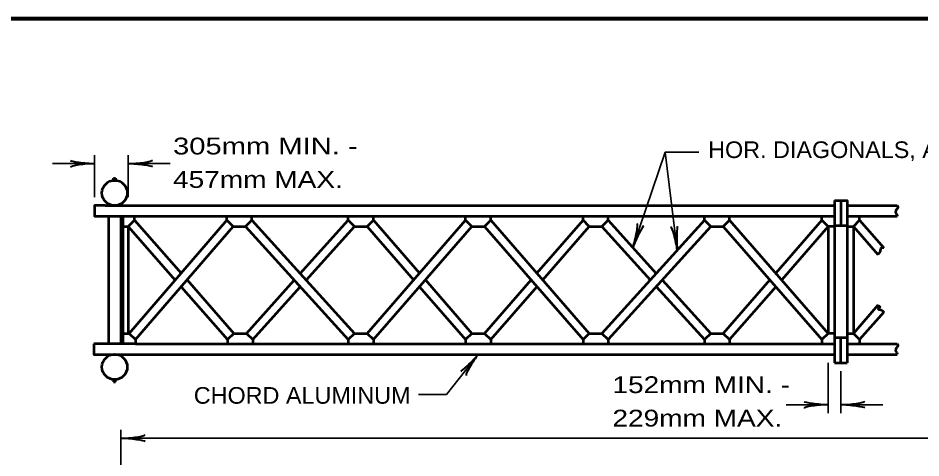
# Model space of a CAD drawing. Extents: x -29 to 827, y -14 to 530.
# Drawn here: x 166.5 to 296.8, y 459.8 to 523.3 of the extents above; entities that cross this region are included whole.
import ezdxf

# ---------------------------------------------------------------- set-up
doc = ezdxf.new("R2010")
doc.units = 0
doc.header["$LTSCALE"] = 0.97
doc.layers.add('1', color=7, linetype='Continuous', lineweight=53)

msp = doc.modelspace()

# ---------------------------------------------------------------- linework, layer by layer
at = {"layer": '1', "lineweight": 35}
for p, q in [((177.5755, 497.4045), (177.5755, 503.4525)), ((182.4475, 497.4045), (182.4475, 503.4525)), ((259.9246, 503.8997), (264.7716, 503.8997)), ((171.5275, 502.2525), (177.5755, 502.2525)), ((182.4475, 502.2525), (188.4955, 502.2525)), ((283.4155, 473.5245), (283.4155, 466.2765)), ((285.2395, 472.3245), (285.2395, 466.2765)), ((283.4155, 467.4765), (277.3675, 467.4765)), ((285.2395, 467.4765), (291.2875, 467.4765)), ((181.3915, 424.6845), (181.3915, 463.8525)), ((181.3915, 462.6285), (412.9195, 462.6285))]:
    msp.add_line(p, q, dxfattribs=at)
at = {"layer": '1'}
for p, q in [((180.3355, 500.1405), (180.6235, 500.1405)), ((180.3355, 499.8285), (180.3355, 500.1405)), ((180.6235, 500.1405), (180.6235, 499.8285)), ((284.3275, 496.9485), (284.3275, 473.5245)), ((285.2395, 496.9485), (285.2395, 493.3245)), ((179.0875, 496.2045), (284.3275, 496.2045)), ((286.1515, 496.2045), (293.3995, 496.2045)), ((179.5675, 494.6925), (179.5675, 476.2365)), ((181.3915, 494.6925), (181.3915, 476.2365)), ((181.6795, 494.6925), (181.6795, 476.2365)), ((182.4475, 493.1805), (183.3595, 494.0925)), ((182.5675, 477.7485), (196.6555, 494.0925)), ((183.3595, 494.0925), (183.3595, 494.6925)), ((183.3595, 494.6925), (231.1195, 494.6925)), ((183.3595, 494.0925), (190.0555, 486.4365)), ((196.6555, 494.0925), (196.6555, 494.6925)), ((197.5675, 493.1805), (196.6555, 494.0925)), ((199.3675, 493.1805), (200.2795, 494.0925)), ((200.2795, 494.0925), (200.2795, 494.6925)), ((200.2795, 494.0925), (215.0875, 477.7485)), ((207.2635, 486.3885), (214.1755, 494.0925)), ((214.1755, 494.0925), (214.1755, 494.6925)), ((215.0875, 493.1805), (214.1755, 494.0925)), ((216.9115, 477.7485), (231.1195, 494.0925)), ((216.9115, 493.1805), (217.8235, 494.0925)), ((217.8235, 494.0925), (217.8235, 494.6925)), ((217.8235, 494.0925), (224.4715, 486.4365)), ((231.1195, 494.0925), (231.1195, 494.6925)), ((232.0315, 493.1805), (231.1195, 494.0925)), ((233.8315, 493.1805), (234.7435, 494.0925)), ((234.7435, 494.0925), (234.7435, 494.6925)), ((234.7435, 494.0925), (248.9515, 477.7485)), ((241.3915, 486.4365), (248.0635, 494.0925)), ((248.0635, 494.0925), (248.0635, 494.6925)), ((248.9515, 493.1805), (248.0635, 494.0925)), ((250.7755, 493.1805), (251.6875, 494.0925)), ((265.5835, 494.0925), (250.7755, 477.7485)), ((251.6875, 494.0925), (251.6875, 494.6925)), ((251.6875, 494.0925), (258.6235, 486.4125)), ((265.5835, 494.0925), (265.5835, 494.6925)), ((266.4955, 493.1805), (265.5835, 494.0925)), ((268.2955, 493.1805), (269.2075, 494.0925)), ((269.2075, 494.0925), (269.2075, 494.6925)), ((269.2075, 494.0925), (283.4155, 477.7485)), ((282.5275, 494.0925), (275.8555, 486.4365)), ((282.5275, 494.0925), (282.5275, 494.6925)), ((283.4155, 493.1805), (282.5275, 494.0925)), ((286.1515, 494.6925), (293.3995, 494.6925)), ((287.0635, 493.1805), (287.9515, 494.0925)), ((287.9515, 494.0925), (287.9515, 494.6925)), ((287.9515, 494.0925), (291.4315, 490.0845)), ((181.6795, 493.1805), (182.4475, 493.1805)), ((182.4475, 493.1805), (189.2155, 485.4525)), ((182.4475, 493.1805), (182.4475, 477.7485)), ((183.4795, 476.8605), (197.5675, 493.1805)), ((199.3675, 493.1805), (214.1755, 476.8605)), ((208.1275, 485.4285), (215.0875, 493.1805)), ((216.9115, 493.1805), (223.6075, 485.4765)), ((217.8235, 476.8605), (232.0315, 493.1805)), ((233.8315, 493.1805), (248.0635, 476.8605)), ((242.2555, 485.4765), (248.9515, 493.1805)), ((250.7755, 493.1805), (257.7595, 485.4765)), ((266.4955, 493.1805), (251.6875, 476.8605)), ((268.2955, 493.1805), (282.5275, 476.8605)), ((283.4155, 493.1805), (276.7195, 485.4765)), ((284.3275, 493.1805), (283.4155, 493.1805)), ((283.4155, 493.1805), (283.4155, 477.7485)), ((284.3275, 493.3245), (286.1515, 493.3245)), ((286.1515, 493.1805), (287.0635, 493.1805)), ((287.0635, 493.1805), (287.0635, 477.7485)), ((287.0635, 493.1805), (290.5915, 489.1245)), ((190.9195, 485.4765), (197.6875, 477.7485)), ((199.5115, 477.7485), (206.3995, 485.4285)), ((225.3115, 485.4765), (232.0315, 477.7485)), ((233.8315, 477.7485), (240.5515, 485.4765)), ((259.4875, 485.4765), (266.4955, 477.7485)), ((275.0155, 485.4765), (268.2955, 477.7485)), ((190.0555, 484.4925), (196.7755, 476.8605)), ((200.3995, 476.8605), (207.2635, 484.4685)), ((224.4715, 484.4925), (231.1195, 476.8605)), ((234.7435, 476.8605), (241.3915, 484.4925)), ((258.6235, 484.5165), (265.5835, 476.8605)), ((275.8555, 484.4925), (269.2075, 476.8605)), ((290.5915, 481.8285), (287.0635, 477.7485)), ((291.4315, 480.8445), (287.9515, 476.8605)), ((181.6795, 477.7485), (182.5675, 477.7485)), ((182.5675, 477.7485), (183.4795, 476.8605)), ((183.4795, 476.8605), (183.4795, 476.2365)), ((197.6875, 477.7485), (196.7755, 476.8605)), ((196.7755, 476.8605), (196.7755, 476.2365)), ((197.6875, 477.7485), (199.5115, 477.7485)), ((199.5115, 477.7485), (200.3995, 476.8605)), ((200.3995, 476.8605), (200.3995, 476.2365)), ((215.0875, 477.7485), (214.1755, 476.8605)), ((214.1755, 476.8605), (214.1755, 476.2365)), ((215.0875, 477.7485), (216.9115, 477.7485)), ((216.9115, 477.7485), (217.8235, 476.8605)), ((217.8235, 476.8605), (217.8235, 476.2365)), ((232.0315, 477.7485), (231.1195, 476.8605)), ((231.1195, 476.8605), (231.1195, 476.2365)), ((232.0315, 477.7485), (233.8315, 477.7485)), ((233.8315, 477.7485), (234.7435, 476.8605)), ((234.7435, 476.8605), (234.7435, 476.2365)), ((248.9515, 477.7485), (248.0635, 476.8605)), ((248.0635, 476.8605), (248.0635, 476.2365)), ((248.9515, 477.7485), (250.7755, 477.7485)), ((250.7755, 477.7485), (251.6875, 476.8605)), ((251.6875, 476.8605), (251.6875, 476.2365)), ((266.4955, 477.7485), (265.5835, 476.8605)), ((265.5835, 476.8605), (265.5835, 476.2365)), ((266.4955, 477.7485), (268.2955, 477.7485)), ((268.2955, 477.7485), (269.2075, 476.8605)), ((269.2075, 476.8605), (269.2075, 476.2365)), ((283.4155, 477.7485), (282.5275, 476.8605)), ((282.5275, 476.8605), (282.5275, 476.2365)), ((284.3275, 477.7485), (283.4155, 477.7485)), ((284.3275, 477.1485), (286.1515, 477.1485)), ((285.2395, 473.5245), (285.2395, 477.1485)), ((286.1515, 477.7485), (287.0635, 477.7485)), ((287.0635, 477.7485), (287.9515, 476.8605)), ((287.9515, 476.8605), (287.9515, 476.2365)), ((179.5675, 476.2365), (177.4555, 476.2365)), ((183.4795, 476.2365), (231.1195, 476.2365)), ((286.1515, 476.2365), (293.3995, 476.2365)), ((178.9435, 474.7245), (284.3275, 474.7245)), ((286.1515, 474.7245), (293.3995, 474.7245)), ((284.3275, 473.5245), (286.1515, 473.5245)), ((180.3355, 471.1005), (180.3355, 470.7885)), ((180.3355, 470.7885), (180.6235, 470.7885)), ((180.6235, 470.7885), (180.6235, 471.1005))]:
    msp.add_line(p, q, dxfattribs=at)
at = {"layer": '1', "lineweight": 158}
msp.add_lwpolyline([(820.0407, 523.2545), (28.3407, 523.1545), (28.4407, -2.8455)], dxfattribs=at)
at = {"layer": '1', "lineweight": 35}
for points in [[(255.2327, 490.167), (259.9246, 503.8997), (261.6496, 489.7505)], [(232.9483, 474.7245), (228.3353, 468.9563), (224.324, 468.9563)]]:
    msp.add_lwpolyline(points, dxfattribs=at)
at = {"layer": '1'}
for points in [[(284.3275, 496.9485), (286.1515, 496.9485), (286.1515, 473.5245)], [(179.0875, 496.2045), (177.5755, 496.2045), (177.5755, 494.6925), (183.3595, 494.6925)], [(231.1195, 494.6925), (234.7435, 494.6925), (282.5275, 494.6925), (284.3275, 494.6925)], [(197.5675, 493.1805), (198.4795, 493.1805), (199.3675, 493.1805)], [(215.0875, 493.1805), (215.9995, 493.1805), (216.9115, 493.1805)], [(232.0315, 493.1805), (232.9435, 493.1805), (233.8315, 493.1805)], [(248.9515, 493.1805), (249.8635, 493.1805), (250.7755, 493.1805)], [(266.4955, 493.1805), (267.4075, 493.1805), (268.2955, 493.1805)], [(177.4555, 476.2365), (177.4555, 474.7245), (178.9435, 474.7245)], [(183.4795, 476.2365), (181.3915, 476.2365), (179.5675, 476.2365)], [(231.1195, 476.2365), (234.7435, 476.2365), (282.5275, 476.2365), (284.3275, 476.2365)]]:
    msp.add_lwpolyline(points, dxfattribs=at)
for centre in [(180.4765, 498.0179), (180.4765, 472.9187)]:
    msp.add_circle(centre, 1.8265, dxfattribs=at)
at = {"layer": '1', "lineweight": 40}
for centre, major_axis, ratio, start_param, end_param in [((176.2674, 501.9173), (2.16, 0.1889), 0.122415, 0.89635335, 3.14159265), ((176.2674, 501.9173), (2.16, 0.1889), 0.122415, 0.89635335, 3.14159265), ((176.232, 502.5075), (2.1246, -0.2125), 0.07063, 3.14071475, 5.41810995), ((176.232, 502.5075), (2.1246, -0.2125), 0.07063, 3.14071475, 5.41810995), ((183.7964, 501.9956), (-2.1246, 0.2125), 0.07063, 3.14071475, 5.41810995), ((183.761, 502.5857), (-2.16, -0.1889), 0.122415, 0.89635335, 3.14159265), ((255.3423, 491.5133), (-0.5155, -2.0883), 0.122415, 0.89635335, 3.14159265), ((255.9077, 491.3573), (0.8809, 1.9264), 0.07063, 6.28230741, 8.55970261), ((261.162, 491.0102), (0.4453, -2.1044), 0.122415, 0.89635335, 3.14159265), ((261.7389, 491.1159), (-0.0458, 2.1178), 0.07063, 6.28230741, 8.55970261), ((231.9102, 473.833), (-1.481, -1.5144), 0.07063, 6.28230741, 8.55970261), ((232.3894, 473.4948), (1.192, 1.7905), 0.122415, 0.89635335, 3.14159265), ((282.072, 467.7315), (2.1246, -0.2125), 0.07063, 3.14071475, 5.41810995), ((286.5617, 467.8097), (-2.16, -0.1889), 0.122415, 0.89635335, 3.14159265), ((286.5617, 467.8097), (-2.16, -0.1889), 0.122415, 0.89635335, 3.14159265), ((282.1074, 467.1413), (2.16, 0.1889), 0.122415, 0.89635335, 3.14159265), ((286.5971, 467.2196), (-2.1246, 0.2125), 0.07063, 3.14071475, 5.41810995), ((286.5971, 467.2196), (-2.1246, 0.2125), 0.07063, 3.14071475, 5.41810995), ((182.739, 462.3813), (-2.1246, 0.2125), 0.07063, 3.14071475, 5.41810995), ((182.7036, 462.9714), (-2.16, -0.1889), 0.122415, 0.89635335, 3.14159265)]:
    msp.add_ellipse(centre, major_axis=major_axis, ratio=ratio, start_param=start_param, end_param=end_param, dxfattribs=at)
at = {"layer": '1'}
for points in [[(293.3995, 496.2045), (293.4715, 495.9165), (293.2555, 495.5805), (293.1595, 495.1965), (293.3275, 494.8845), (293.3995, 494.6925)], [(291.4315, 490.0845), (291.0475, 490.0605), (290.9035, 489.5565), (290.5915, 489.1245)], [(290.5915, 481.8285), (290.8555, 481.5405), (290.6395, 481.3005), (290.9995, 481.1565), (291.4315, 480.8445)], [(293.3995, 476.2605), (293.4715, 475.9725), (293.2555, 475.6365), (293.1595, 475.2525), (293.3275, 474.9405), (293.3995, 474.7485)]]:
    msp.add_spline(points, degree=3, dxfattribs=at)

# ---------------------------------------------------------------- texts
for s, height, width, p in [('305mm MIN. -', 2.419, 1.3, (188.9037, 503.5821)), ('HOR. DIAGONALS, ALUMINUM', 2.4, 1.05, (266.1088, 503.0638)), ('457mm MAX.', 2.419, 1.25, (188.9037, 498.7629)), ('152mm MIN. -', 2.419, 1.25, (252.3, 469.1517)), ('CHORD ALUMINUM', 2.4, 1.05, (191.899, 467.6188)), ('229mm MAX.', 2.419, 1.25, (252.3, 464.3325))]:
    msp.add_text(s, height=height, dxfattribs=dict(at, width=width)).set_placement(p)

doc.saveas('drawing.dxf')
